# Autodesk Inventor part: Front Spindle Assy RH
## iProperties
Shininess: 70.0
Angle Display Precision: 2
Document Length Units: 11269
Document Angle Units: 11279
Document Time Units: 11290
Document Mass Units: 11283
Document Length Units Precision: 3
Document Angle Units Precision: 2
Compacted: True
Created: 2001-08
Part Number: Front Spindle Assy RH
Document SubType Name: Modeling
Designer: Martin Budgell
Density: 0.0
Volumn: 0.0
Area: 0.0
PropertySet Name: Model Information
Control State: 0
Master: False
Checked Out: False
Author: Martin Budgell
